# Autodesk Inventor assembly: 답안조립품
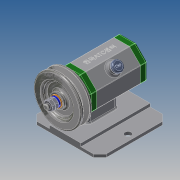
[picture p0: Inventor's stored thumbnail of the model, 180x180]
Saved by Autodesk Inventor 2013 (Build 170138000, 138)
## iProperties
Created: 2018-06
Part Number: 답안조립품
Document SubType Name: Assembly
Designer: doa
Author: doa
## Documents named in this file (16)
- C:\Users\doa\Desktop\480607V1018\답안조립품.iam
- C:\Users\doa\Desktop\480607V1018\본체.ipt
- C:\Users\doa\Desktop\480607V1018\베어링 15x32x9.ipt
- C:\Users\doa\Desktop\480607V1018\뒤커버.ipt
- C:\Users\doa\Desktop\480607V1018\앞커버.ipt
- C:\Users\doa\Desktop\480607V1018\오일 실 15 25 7.ipt
- C:\Users\doa\Desktop\480607V1018\볼트 M4x12.ipt
- C:\Users\doa\Desktop\480607V1018\축.ipt
- C:\Users\doa\Desktop\480607V1018\키 3x3x12.ipt
- 키 3x3x12.ipt
- C:\Users\doa\Desktop\480607V1018\V벨트풀리.ipt
- C:\Users\doa\Desktop\480607V1018\와셔 8x17.ipt
- C:\Users\doa\Desktop\480607V1018\스프링와셔 8.ipt
- C:\Users\doa\Desktop\480607V1018\너트 M8.ipt
- 너트 M8.ipt
- C:\Users\doa\Desktop\480607V1018\고무캡.ipt
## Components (2 placed, 2 different names)
1. V벨트풀리:1 — 각도:2
2. 고무캡:1
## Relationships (1: Angle 1)
- 각도:2 [Angle]: V벨트풀리:1
